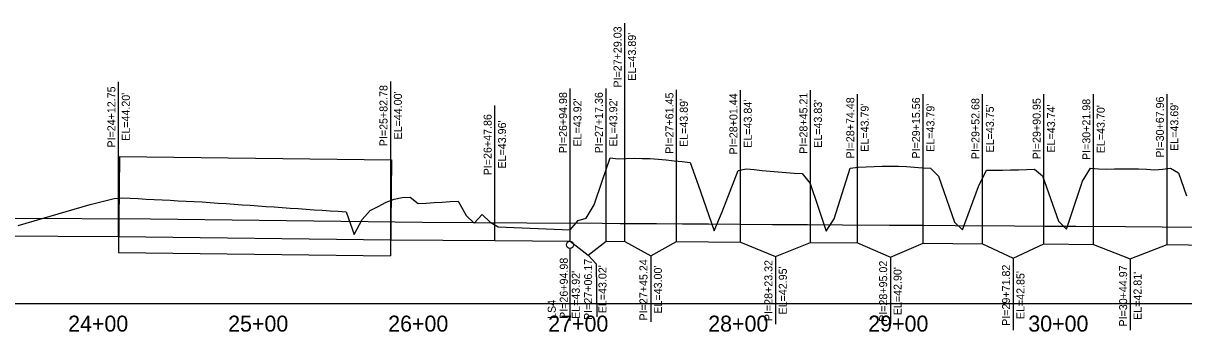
# Model space of a CAD drawing. Extents: x 2394206 to 2397081, y 556531 to 561531.
# Drawn here: x 2395634 to 2396359, y 559014 to 559207 of the extents above; entities that cross this region are included whole.
import ezdxf

# ---------------------------------------------------------------- set-up
doc = ezdxf.new("R2010")
doc.units = 0
for name, color, linetype in [('Default', 7, 'Continuous'), ('Existing ground', 7, 'Continuous'), ('Profile grid', 7, 'Continuous'), ('Proposed bankfull', 7, 'Continuous'), ('Proposed Culvert', 7, 'Continuous'), ('Proposed structure lables', 7, 'Continuous'), ('Station lables', 7, 'Continuous')]:
    doc.layers.add(name, color=color, linetype=linetype)

msp = doc.modelspace()

# ---------------------------------------------------------------- linework, layer by layer
at = {"layer": 'Default'}
for p, q in [((2396009.87, 559070.09), (2396009.87, 559206.67)), ((2395693.59, 559073.18), (2395693.59, 559169.91)), ((2395863.62, 559071.18), (2395863.62, 559170.27)), ((2395975.82, 559070.36), (2395975.82, 559165.85)), ((2395998.2, 559070.34), (2395998.2, 559165.85)), ((2396042.29, 559070.06), (2396042.29, 559165)), ((2396082.28, 559069.57), (2396082.28, 559164.71)), ((2396126.05, 559069.53), (2396126.05, 559164.71)), ((2396155.32, 559069.13), (2396155.32, 559162.16)), ((2396196.4, 559069.09), (2396196.4, 559162.16)), ((2396233.52, 559068.65), (2396233.52, 559162.16)), ((2396271.79, 559068.61), (2396271.79, 559162.16)), ((2396302.82, 559068.17), (2396302.82, 559162.16)), ((2396348.8, 559068.13), (2396348.8, 559162.16)), ((2395928.7, 559070.77), (2395928.7, 559155.24)), ((2396026.08, 559061.16), (2396026.08, 559019.81)), ((2396104.16, 559060.67), (2396104.16, 559018.25)), ((2396175.86, 559060.22), (2396175.86, 559018.25)), ((2396252.66, 559059.73), (2396252.66, 559014.54)), ((2396325.81, 559059.27), (2396325.81, 559014.54))]:
    msp.add_line(p, q, dxfattribs=at)
msp.add_lwpolyline([(2395987.01, 559061.41), (2395991.96, 559056.09), (2395992.35, 559022.84)], dxfattribs=at)
at = {"layer": 'Existing ground'}
for points in [[(2395780.84, 559092.38), (2395785.84, 559092.03), (2395790.84, 559091.69), (2395795.84, 559091.35), (2395800.84, 559091), (2395805.84, 559090.66), (2395810.84, 559090.32), (2395815.84, 559089.97), (2395820.84, 559089.63), (2395825.84, 559089.29), (2395830.84, 559088.94), (2395835.84, 559088.6), (2395840.84, 559074.48), (2395845.84, 559083.8), (2395850.84, 559089.45), (2395855.84, 559092.01), (2395860.84, 559094.57), (2395865.84, 559096.46), (2395870.84, 559097.5), (2395875.84, 559097.81), (2395880.84, 559093.84), (2395885.84, 559094.14), (2395890.84, 559094.44), (2395895.84, 559094.74), (2395900.84, 559095.04), (2395905.84, 559095.34), (2395910.84, 559086.38), (2395915.84, 559081.45), (2395920.84, 559087.05), (2395925.84, 559082.08), (2395930.84, 559079.15), (2395935.84, 559078.96), (2395940.84, 559078.76), (2395945.84, 559078.56), (2395950.84, 559078.37), (2395955.84, 559078.17), (2395960.84, 559077.98), (2395965.84, 559077.78), (2395970.84, 559077.59), (2395975.84, 559077.39), (2395980.84, 559083.17), (2395985.84, 559084.58), (2395990.84, 559093), (2395995.84, 559107.83), (2396000.84, 559122.48), (2396005.84, 559121.82), (2396010.84, 559122.03), (2396015.84, 559122.13), (2396020.84, 559122.09), (2396025.84, 559121.91), (2396030.84, 559121.59), (2396035.84, 559121.16), (2396040.84, 559120.62), (2396045.84, 559120.04), (2396050.84, 559119.45), (2396055.84, 559105.42), (2396060.84, 559091.1), (2396065.84, 559076.77), (2396070.84, 559088.71), (2396075.84, 559101.6), (2396080.84, 559114.49), (2396085.84, 559115.55), (2396090.84, 559115.04), (2396095.84, 559114.54), (2396100.84, 559114.06), (2396105.84, 559113.61), (2396110.84, 559113.2), (2396115.84, 559112.86), (2396120.84, 559112.68), (2396125.84, 559106.31), (2396130.84, 559091.45), (2396135.84, 559076.59), (2396140.84, 559084.25), (2396145.84, 559100.11), (2396150.84, 559115.98), (2396155.84, 559116.48), (2396160.84, 559116.81), (2396165.84, 559117.05), (2396170.84, 559117.19), (2396175.84, 559117.21), (2396180.84, 559117.11), (2396185.84, 559116.91), (2396190.84, 559116.6), (2396195.84, 559116.21), (2396200.84, 559115.99), (2396205.84, 559110.9), (2396210.84, 559096.53), (2396215.84, 559082.15), (2396220.84, 559077.46), (2396225.84, 559090.95), (2396230.84, 559104.44), (2396235.84, 559114.74), (2396240.84, 559114.71), (2396245.84, 559114.73), (2396250.84, 559114.81), (2396255.84, 559114.93), (2396260.84, 559115.1), (2396265.84, 559115.31), (2396270.84, 559111.21), (2396275.84, 559096.88), (2396280.84, 559082.7)], [(2396280.84, 559082.7), (2396285.84, 559077.84), (2396290.84, 559092.7), (2396295.84, 559107.84), (2396300.84, 559116.05), (2396305.84, 559115.43), (2396310.84, 559115.27), (2396315.84, 559115.46), (2396320.84, 559115.56), (2396325.84, 559115.55), (2396330.84, 559115.45), (2396335.84, 559115.25), (2396340.84, 559114.96), (2396345.84, 559115.26), (2396350.84, 559115.85), (2396355.84, 559112.93), (2396360.84, 559098.53)], [(2395630.84, 559080.17), (2395635.84, 559081.62), (2395640.84, 559083.07), (2395645.84, 559084.52), (2395650.84, 559085.97), (2395655.84, 559087.42), (2395660.84, 559088.87), (2395665.84, 559090.32), (2395670.84, 559091.77), (2395675.84, 559093.22), (2395680.84, 559094.46), (2395685.84, 559095.67), (2395690.84, 559096.89), (2395695.84, 559097.44), (2395700.84, 559097.17), (2395705.84, 559096.91), (2395710.84, 559096.65), (2395715.84, 559096.39), (2395720.84, 559096.12), (2395725.84, 559095.86), (2395730.84, 559095.6), (2395735.84, 559095.33), (2395740.84, 559095.07), (2395745.84, 559094.78), (2395750.84, 559094.43), (2395755.84, 559094.09), (2395760.84, 559093.75), (2395765.84, 559093.4), (2395770.84, 559093.06), (2395775.84, 559092.72), (2395780.84, 559092.38)]]:
    msp.add_lwpolyline(points, dxfattribs=at)
at = {"layer": 'Profile grid'}
msp.add_line((2394280.84, 559031.18), (2397080.84, 559031.18), dxfattribs=at)
at = {"layer": 'Proposed bankfull'}
msp.add_lwpolyline([(2395627.82, 559084.69), (2395713.53, 559084.18), (2395883.56, 559082.18), (2395948.64, 559081.77), (2395995.76, 559081.47), (2396006.95, 559081.39), (2396018.14, 559081.32), (2396029.81, 559081.25), (2396046.02, 559081.14), (2396062.23, 559081.04), (2396102.22, 559080.78), (2396124.1, 559080.64), (2396145.99, 559080.5), (2396175.26, 559080.31), (2396195.8, 559080.18), (2396216.34, 559080.05), (2396253.46, 559079.81), (2396272.6, 559079.69), (2396291.73, 559079.57), (2396322.76, 559079.37), (2396345.75, 559079.22), (2396368.74, 559079.08)], dxfattribs=at)
at = {"layer": 'Proposed Culvert'}
for p, q in [((2395694.18, 559123.18), (2395693.47, 559063.18)), ((2395694.18, 559123.18), (2395864.21, 559121.18)), ((2395864.21, 559121.18), (2395863.5, 559061.18)), ((2395693.47, 559063.18), (2395863.5, 559061.18))]:
    msp.add_line(p, q, dxfattribs=at)
at = {"layer": 'Proposed structure lables'}
for p, q in [((2395512.69, 559074.26), (2395693.59, 559073.18)), ((2395693.59, 559073.18), (2395863.62, 559071.18)), ((2395863.62, 559071.18), (2395928.7, 559070.77)), ((2395928.7, 559070.77), (2395975.82, 559070.36)), ((2395975.64, 559065.7), (2395975.64, 559020.33)), ((2395975.82, 559070.36), (2395987.01, 559061.41)), ((2395987.01, 559061.41), (2395998.2, 559070.34)), ((2395998.2, 559070.34), (2396009.87, 559070.09)), ((2396009.87, 559070.09), (2396026.08, 559061.16)), ((2396026.08, 559061.16), (2396042.29, 559070.06)), ((2396042.29, 559070.06), (2396082.28, 559069.57)), ((2396082.28, 559069.57), (2396104.16, 559060.67)), ((2396104.16, 559060.67), (2396126.05, 559069.53)), ((2396126.05, 559069.53), (2396155.32, 559069.13)), ((2396155.32, 559069.13), (2396175.86, 559060.22)), ((2396175.86, 559060.22), (2396196.4, 559069.09)), ((2396196.4, 559069.09), (2396233.52, 559068.65)), ((2396233.52, 559068.65), (2396252.66, 559059.73)), ((2396252.66, 559059.73), (2396271.79, 559068.61)), ((2396271.79, 559068.61), (2396302.82, 559068.17)), ((2396302.82, 559068.17), (2396325.81, 559059.27)), ((2396325.81, 559059.27), (2396348.8, 559068.13)), ((2396348.8, 559068.13), (2396379.18, 559067.7))]:
    msp.add_line(p, q, dxfattribs=at)
msp.add_ellipse((2395975.64, 559067.99), major_axis=(0, -2.29), ratio=0.950348, dxfattribs=at)

# ---------------------------------------------------------------- texts
for s, p in [('PI=27+29.03', (2396007.87, 559166.37)), ("EL=43.89'", (2396016.87, 559170.62)), ('PI=24+12.75', (2395691.59, 559128.81)), ('PI=25+82.78', (2395861.62, 559129.66)), ("EL=44.20'", (2395700.59, 559133.06)), ("EL=44.00'", (2395870.62, 559133.9)), ('PI=26+94.98', (2395973.82, 559125.25)), ("EL=43.92'", (2395982.82, 559129.5)), ('PI=27+17.36', (2395996.2, 559125.23)), ("EL=43.92'", (2396005.2, 559129.47)), ('PI=27+61.45', (2396040.29, 559124.95)), ("EL=43.89'", (2396049.29, 559129.2)), ('PI=28+01.44', (2396080.28, 559124.47)), ("EL=43.84'", (2396089.28, 559128.71)), ('PI=28+45.21', (2396124.05, 559124.89)), ("EL=43.83'", (2396133.05, 559128.67)), ('PI=28+74.48', (2396153.32, 559121.99)), ('PI=29+15.56', (2396194.4, 559121.95)), ('PI=29+52.68', (2396231.52, 559121.51)), ('PI=29+90.95', (2396269.79, 559121.48)), ('PI=30+21.98', (2396300.82, 559121.04)), ('PI=30+67.96', (2396346.8, 559122.51)), ("EL=43.79'", (2396162.32, 559126.24)), ("EL=43.79'", (2396203.4, 559126.2)), ("EL=43.75'", (2396240.52, 559125.76)), ("EL=43.74'", (2396278.79, 559125.72)), ("EL=43.70'", (2396309.82, 559125.28)), ("EL=43.69'", (2396355.8, 559126.76)), ('PI=26+47.86', (2395926.7, 559111.47)), ("EL=43.96'", (2395935.7, 559115.71)), ('PI=26+94.98', (2395974.28, 559021.61)), ('PI=27+06.17', (2395989.46, 559020.94)), ('PI=27+45.24', (2396024.08, 559020.65)), ('PI=28+23.32', (2396102.16, 559020.2)), ('PI=28+95.02', (2396173.86, 559019.75)), ("EL=43.92'", (2395981.78, 559021.61)), ("EL=43.02'", (2395998.46, 559025.14)), ("EL=43.00'", (2396033.08, 559024.9)), ("EL=42.95'", (2396111.16, 559024.4)), ("EL=42.90'", (2396182.86, 559023.95)), ('PI=29+71.82', (2396250.66, 559017.28)), ("EL=42.85'", (2396259.66, 559021.48)), ('PI=30+44.97', (2396323.81, 559016.82)), ("EL=42.81'", (2396332.81, 559021.02)), ('LS4', (2395966.78, 559021.61))]:
    msp.add_text(s, height=5, rotation=90, dxfattribs=at).set_placement(p)
at = {"layer": 'Station lables'}
for s, p in [('24+00', (2395662.05, 559013.68)), ('25+00', (2395762.05, 559013.68)), ('26+00', (2395862.05, 559013.68)), ('27+00', (2395962.05, 559013.68)), ('28+00', (2396062.05, 559013.68)), ('29+00', (2396162.05, 559013.68)), ('30+00', (2396262.05, 559013.68))]:
    msp.add_text(s, height=10, dxfattribs=at).set_placement(p)

doc.saveas('drawing.dxf')
